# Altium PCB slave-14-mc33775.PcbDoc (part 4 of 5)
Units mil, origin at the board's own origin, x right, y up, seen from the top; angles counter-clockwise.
Board outline 6299.21 x 3937.01 mil, 6 copper layers (Top Copper, Supply, Signal Layer 1, Signal Layer 2, GND, Bot Copper), stack 69.773 mil thick; 428 components, 213 nets, 1149 pads, 1672 vias.
Unrouted connection lines stored in the file: 1.
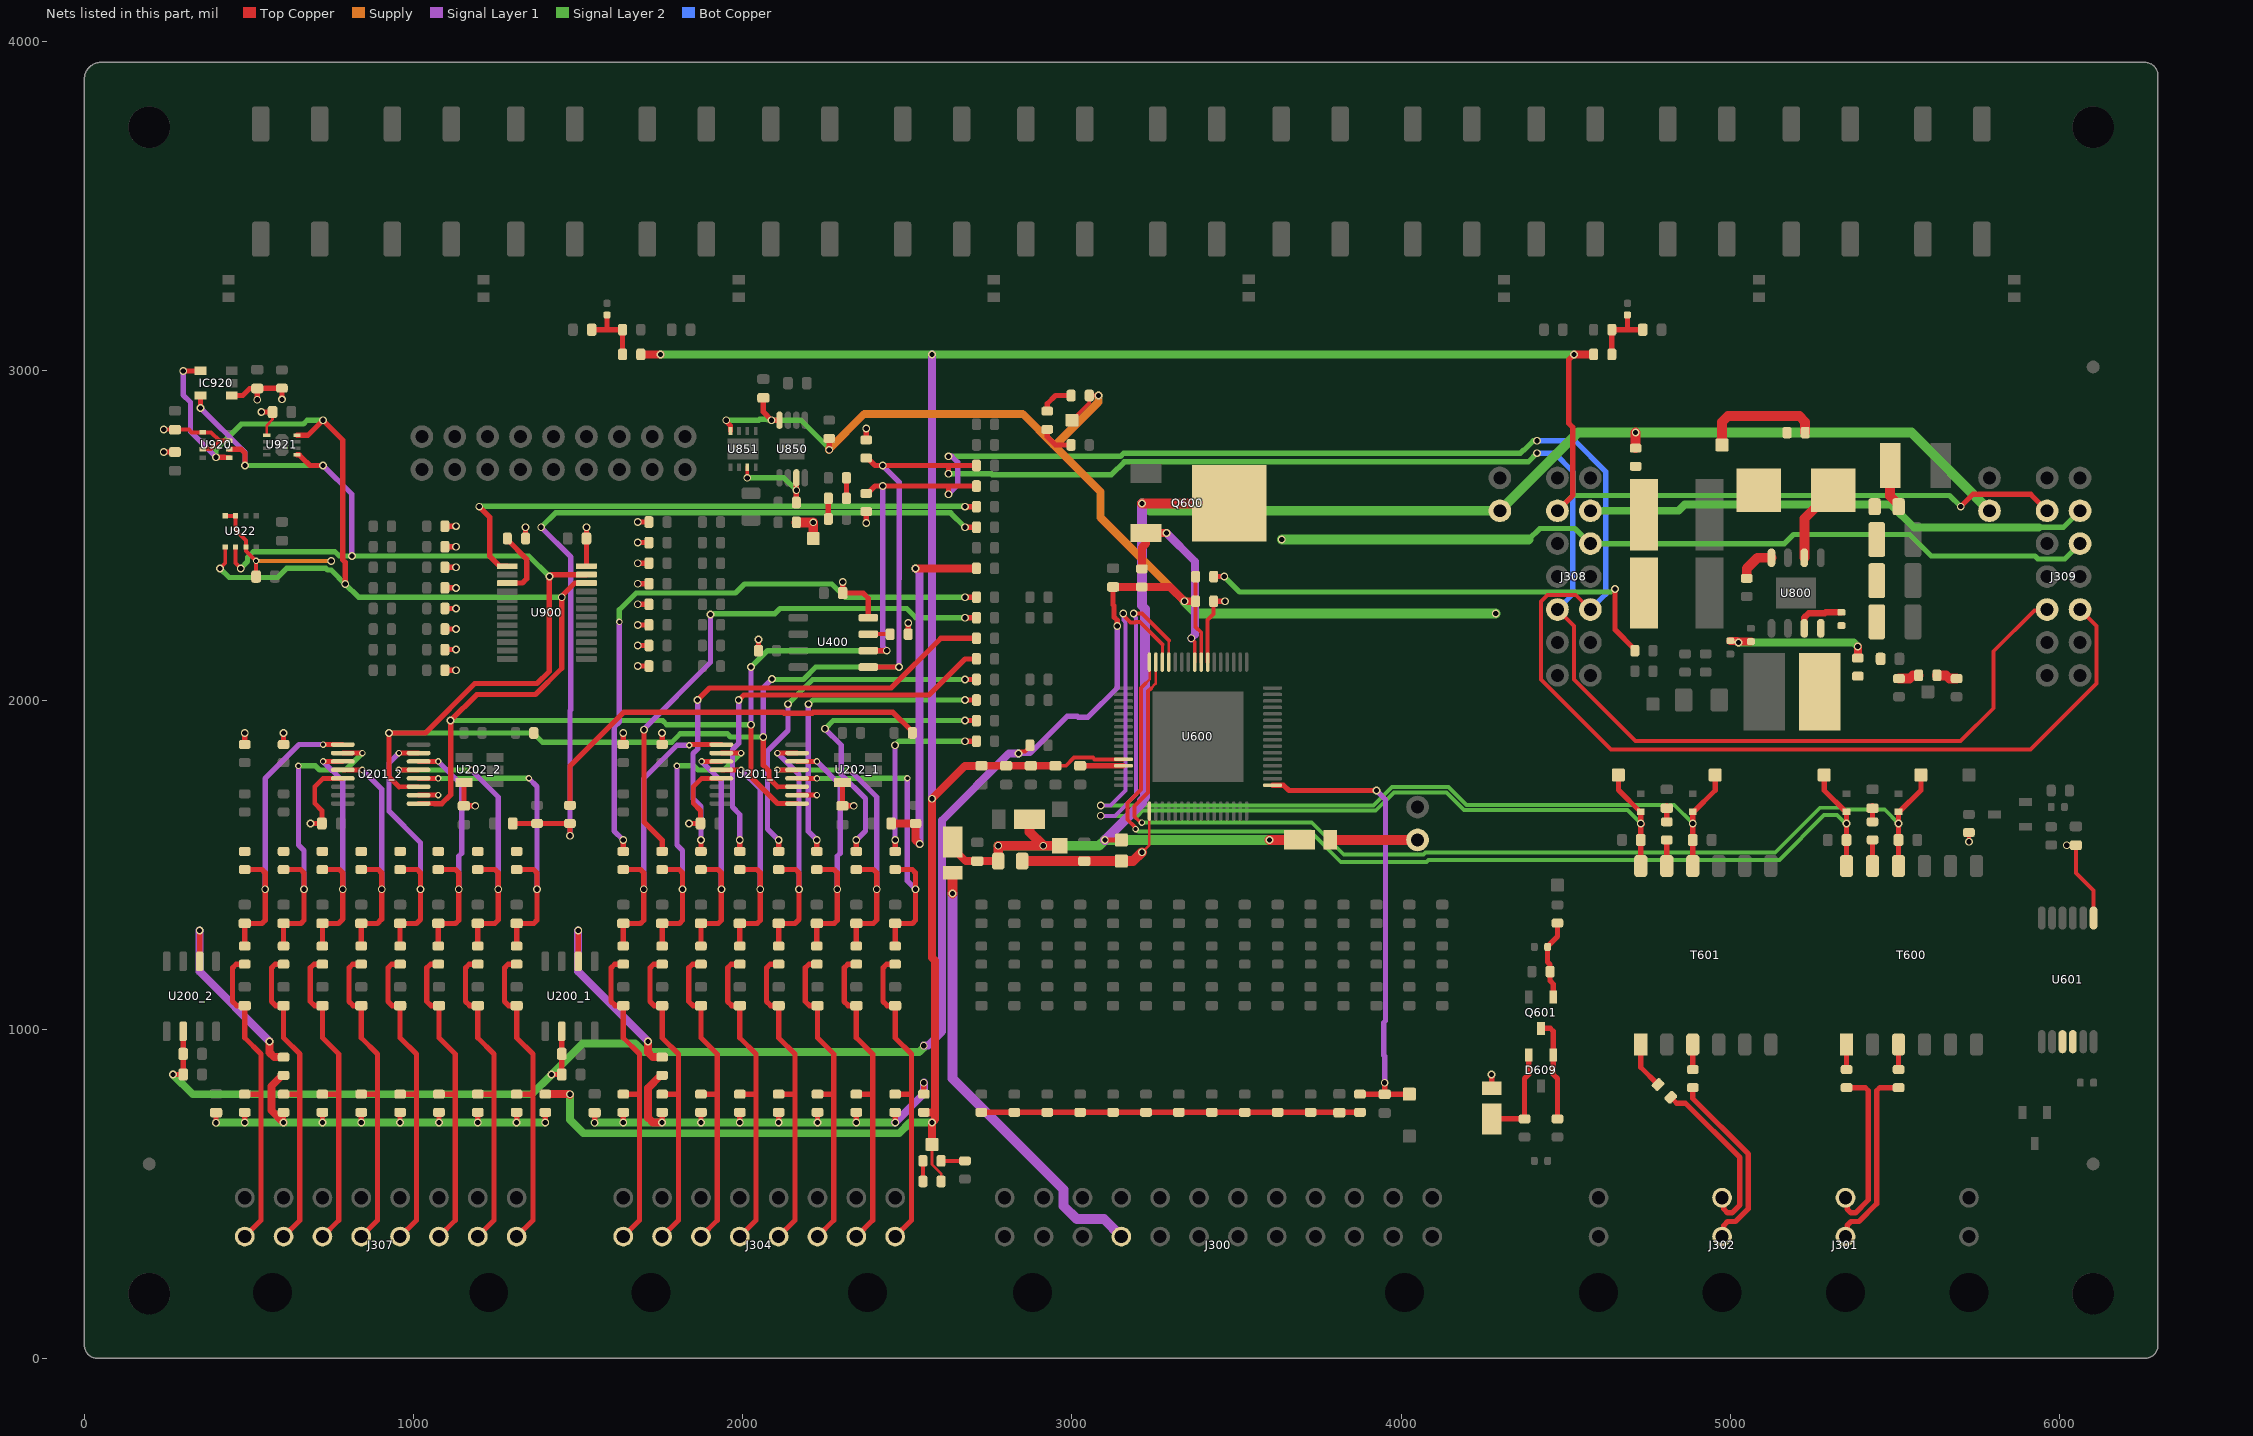
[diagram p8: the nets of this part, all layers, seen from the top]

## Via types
v1: diameter 23.62, hole 15.75, Top Copper to Bot Copper, 1585 vias
v2: diameter 19.68, hole 11.81, Top Copper to Bot Copper, 87 vias

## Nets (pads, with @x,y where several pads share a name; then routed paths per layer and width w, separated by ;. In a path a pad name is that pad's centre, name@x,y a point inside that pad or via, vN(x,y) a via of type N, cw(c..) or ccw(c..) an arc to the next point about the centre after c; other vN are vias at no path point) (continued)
I2C.SCL: IC920.4 J308.5 J309.5 R615.1 R616.1 U201_1.1 U201_2.1 U400.6 U900.22 U920.4 U921.4 U922.4 | length 11567.5
  Top Copper w12: v1(412.01,2400) 427.76,2415.75 U922.4@427.76,2465.26 ; J308.5@4575,2275 4530.55,2319.45 4444.45,2319.45 4425,2300 4425,2062.14 4637.14,1850 5912.5,1850 6112.5,2050 6112.5,2225 J309.5@6062.5,2275
  Top Copper w15: 2105.32,1685.43 U201_1.1@2165.16,1685.43
  Top Copper w16: v1(300,2999.9) 300.1,2999.9 IC920.4@352.76,2999.9 ; v1(400,2737.5) 425.63,2737.5 426.51,2736.61 U920.4@440.35,2736.61 ; U921.4@646.06,2804.53 679.53,2804.53 v1(725,2850) 784.69,2790.31 784.69,2425.98 792.13,2418.54 v1(792.13,2352.69) ; U201_2.1@1015.16,1685.43 1064.04,1685.43 1064.3,1685.18 1085.7,1685.18 1112.5,1711.98 v1(1112.5,1937.5) 1192.11,2017.11 1370.39,2017.11 1450,2096.72 v1(1450,2312.5) 1451.46,2313.96 1451.46,2317.27 1489.5,2355.32 U900.22@1525,2355.32 ; v1(2025,1925) 2025,1765.75 2105.32,1685.43 ; R616.1@2375,2627.56 2378.94,2627.56 2401.38,2650 v1(2425,2650) 2625,2650 ; U400.6@2381.3,2150 v1(2437.5,2150) ; v1(2625,2625) 2625,2650 ; R615.1@2709.94,2650 2625,2650
  Signal Layer 1 w16: v1@300,3000 300,2926.83 322.19,2904.64 322.19,2815.31 v1(400,2737.5) ; v1(2025,1925) v1(2025,2100) ; v1(2425,2650) 2425,2162.5 v1(2437.5,2150) ; v1(2625,2625) 2652.81,2652.81 2652.81,2722.19 2634.69,2740.31 v1(2625,2740.31)
  Signal Layer 2 w16: v1(400,2737.5) 400,2761.55 476.8,2838.34 665.17,2838.34 676.83,2850 v1(725,2850) ; v1(412.01,2400) 439.82,2372.19 586.56,2372.19 614.37,2400 733.34,2400 738.48,2394.86 749.96,2394.86 v1(792.13,2352.69) 832.32,2312.5 v1(1450,2312.5) ; v1(1112.5,1937.5) 1756.54,1937.5 1769.04,1925 v1(2025,1925) ; v1(2025,2100) 2075,2150 v1(2437.5,2150) ; v1(2625,2740.31) 3147.7,2740.31 3157.39,2750 4362.5,2750 4372.19,2759.69 4374.02,2759.69 4401.83,2787.5 v1(4412.5,2787.5)
  Bot Copper w16: v1(4412.5,2787.5) 4528.19,2787.5 4621.45,2694.24 4621.45,2321.45 J308.5@4575,2275
I2C.SDA: IC920.5 J308.6 J309.6 R617.1 R620.1 U201_1.3 U201_2.3 U400.5 U900.23 U920.3 U921.1 U922.3 | length 10757.6
  Top Copper w12: U922.3@459.25,2465.26 459.25,2415.75 v1(475,2400) ; J308.6@4475,2275 4525,2225 4525,2062.14 4712.14,1875 5700,1875 5800,1975 5800,2148.19 5924.05,2272.24 5959.74,2272.24 J309.6@5962.5,2275
  Top Copper w15: 955.32,1736.61 U201_2.3@1015.16,1736.61 ; 2105.32,1736.61 U201_1.3@2165.16,1736.61
  Top Copper w16: v1@351.38,2888.88 352.76,2890.26 IC920.5@352.76,2925.1 ; U920.3@440.35,2762.2 475.3,2762.2 487.5,2750 v1(487.5,2712.5) ; U921.1@646.06,2745.47 651.97,2745.47 659.7,2737.74 684.94,2712.5 v1(725,2712.5) ; 955.32,1736.61 925,1766.93 v1(925,1900) 1035.67,1900 1185.67,2050 1375,2050 1412.5,2087.5 v1(1412.5,2375) 1414.56,2375 1420.47,2380.91 U900.23@1525,2380.91 ; v1(2062.5,1887.5) 2062.5,1801.83 2079.47,1784.86 2079.47,1762.46 2105.32,1736.61 ; R617.1@2375,2734.94 2378.94,2734.94 2401.38,2712.5 v1(2425,2712.5) 2625,2712.5 ; U400.5@2381.3,2100 v1(2475,2100) ; v1(2625,2687.5) 2625,2712.5 ; R620.1@2709.94,2712.5 2625,2712.5
  Signal Layer 1 w16: v1@350,2887.5 v1(352.76,2887.5) 487.5,2752.76 v1(487.5,2712.5) ; v1(725,2712.5) 812.5,2625 v1(812.5,2437.5) ; v1(2062.5,1887.5) 2062.5,2037.53 v1(2089.22,2064.25) ; v1(2425,2712.5) 2475,2662.5 2475,2367.59 2474.75,2367.34 2474.75,2100.25 v1(2475,2100)
  Signal Layer 2 w16: v1(475,2400) 495.61,2420.61 495.61,2433.38 512.72,2450.48 761.52,2450.48 774.5,2437.5 v1(812.5,2437.5) 1350,2437.5 v1(1412.5,2375) ; v1(487.5,2712.5) v1(725,2712.5) ; v1(925,1900) 1363.62,1900 1391.72,1871.89 1784.39,1871.89 1809.89,1897.39 1953.19,1897.39 1963.08,1887.5 v1(2062.5,1887.5) ; v1@2087.5,2062.5 2184.22,2062.5 2221.72,2100 v1(2475,2100) ; v1@2087.5,2062.53 v1(2089.22,2064.25) ; v1(2625,2687.5) 2755.39,2687.5 2758.2,2684.69 3120.36,2684.69 3159.26,2723.59 4386.09,2723.59 v1(4412.5,2750)
  Bot Copper w16: v1(4412.5,2750) 4465.69,2750 4521.45,2694.24 4521.45,2321.45 J308.6@4475,2275
Imon_VDDC: Q600.3 R618.1 U600.41 | length 612.7
  Top Copper w12: v1(3362.5,2187.5) 3373.13,2176.87 U600.41@3373.13,2115.26
  Top Copper w24: R618.1@3212.5,2398.62 3212.5,2463.13 3225,2475.63 Q600.3@3225,2507.18 v1(3287.5,2507.18)
  Signal Layer 1 w24: v1(3287.5,2507.18) 3373.42,2421.26 3373.42,2198.42 v1(3362.5,2187.5)
INT: R609.1 U900.1 | length 1741.4
  Top Copper w16: v1(1199.19,2587.5) 1231,2555.69 1231,2437.7 1261.35,2407.35 1283.98,2407.35 U900.1@1284.84,2406.5 ; v1(2675,2587.5) R609.1@2709.94,2587.5
  Signal Layer 2 w16: v1(1199.19,2587.5) 1200.25,2588.56 2673.94,2588.56 v1(2675,2587.5)
MUX-DATA_IN_1: R100.1 R230_1.2 | length 1257.8
  Top Copper w16: R100.1@1475,1680.12 1475,1800 1637.5,1962.5 2123.17,1962.5 2125.98,1959.69 2211.52,1959.69 2214.33,1962.5 2456.5,1962.5 2515.06,1903.94 R230_1.2@2515.06,1900
MUX-DATA_IN_2: R230_2.2
MUX_DATA: C221_1.2 R231_1.2 R606.1 | length 1157.3
  Top Copper w24: C221_1.2@2462.99,1625 R231_1.2@2525,1625 2525,1575 v1(2537.5,1562.5) ; v1(2525,2400) R606.1@2709.94,2400
  Signal Layer 1 w24: v1(2525,2400) 2537.5,2387.5 v1(2537.5,1562.5)
MUX_DATA2: C221_2.2 R100.2 R231_2.2 R608.1 | length 2544.2
  Top Copper w16: C221_2.2@1302.85,1625 1312.99,1625 R231_2.2@1375,1625 R100.2@1475,1625 v1(1475,1587.5) ; v1(2675,2525) R608.1@2709.94,2525
  Signal Layer 1 w16: v1(1387.5,2525) 1477.81,2434.69 1477.81,1970.7 1475,1967.89 v1(1475,1587.5)
  Signal Layer 2 w16: v1(1387.5,2525) 1431.06,2568.56 2631.44,2568.56 v1(2675,2525)
NetC202_1_2: C202_1.2 R200_1.1 R203_1.1 R206_1.2 R207_1.2 R208_1.2 R209_1.2 R218_1.2 R219_1.2 R220_1.2 R221_1.2 | length 1570.5
  Top Copper w16: v1@1550,716.24 C202_1.2@1550,746.46 ; v1@1637.01,717.22 R206_1.2@1637.01,747.44 ; v1@1755,717.22 R218_1.2@1755,747.44 ; v1@1872.99,717.22 R207_1.2@1872.99,747.44 ; v1@1990.98,717.22 R219_1.2@1990.98,747.44 ; v1@2109.02,717.22 R208_1.2@2109.02,747.44 ; v1@2227.01,717.22 R220_1.2@2227.01,747.44 ; v1@2345,717.22 R209_1.2@2345,747.44 ; v1@2462.99,717.22 R221_1.2@2462.99,747.44 ; R200_1.1@2550,806.79 v1@2550,837.01
  Top Copper w24: v1(1755,716.73) 1726.56,716.73 1712.5,730.79 1712.5,821.38 1751.06,859.94 R203_1.1@1755,859.94
  Signal Layer 1 w24: v1(2462.99,716.73) 2550,803.74 v1(2550,837.5)
  Signal Layer 2 w24: v1@1549.51,716.24 v1(1550,715.75) 1550.49,716.24 2462.5,716.24 v1(2462.99,716.73)
  other v1: 1637.01,716.73 1872.99,716.73 1990.98,716.73 2109.02,716.73 2227.01,716.73 2345,716.73
NetC202_2_2: C202_2.2 R200_2.1 R203_2.1 R206_2.2 R207_2.2 R208_2.2 R209_2.2 R218_2.2 R219_2.2 R220_2.2 R221_2.2 | length 1479.5
  Top Copper w16: v1@400,716.24 C202_2.2@400,746.46 ; v1@487.01,717.22 R206_2.2@487.01,747.44 ; v1@605,717.22 R218_2.2@605,747.44 ; v1@722.99,717.22 R207_2.2@722.99,747.44 ; v1@840.98,717.22 R219_2.2@840.98,747.44 ; v1@959.02,717.22 R208_2.2@959.02,747.44 ; v1@1077.01,717.22 R220_2.2@1077.01,747.44 ; v1@1195,717.22 R209_2.2@1195,747.44 ; v1@1312.99,717.22 R221_2.2@1312.99,747.44 ; v1@1400,717.22 R200_2.1@1400,747.44
  Top Copper w24: v1(605,716.73) 567.89,753.84 567.89,826.77 601.06,859.94 R203_2.1@605,859.94
  Signal Layer 2 w24: v1(400,715.75) 400.49,716.24 1312.5,716.24 v1(1312.99,716.73) ; v1@1313.48,716.24 v1(1312.99,716.73) ; v1(1400,716.73) v1(1312.99,716.73)
  other v1: 487.01,716.73 722.99,716.73 840.98,716.73 959.02,716.73 1077.01,716.73 1195,716.73
NetC607_2: C607.2 R611.1 | length 49.8
  Top Copper w16: R611.1@5432.15,1630.12 C607.2@5432.15,1679.9
NetC610_2: C610.2 R621.1 | length 49.8
  Top Copper w16: R621.1@4807.15,1630.12 C610.2@4807.15,1679.92
NetC615_2: C615.2 Q601.G R634.2 R638.1 | length 244.8
  Top Copper w16: Q601.G@4462.4,1097.24 4462.4,1137.6 4452.56,1147.44 R638.1@4452.56,1175 4452.56,1196.72 4445.08,1204.2 C615.2@4445.08,1250 4447.32,1252.24 4447.32,1254.2 4475,1281.89 R634.2@4475,1322.44
NetC700_2: C700.2 R700.1 R702.2 R704.1 | length 213.7
  Top Copper w16: C700.2@1541.04,3125 1587.5,3125 ; R704.1@1587.5,3169.78 1587.5,3125 ; R700.1@1634.94,3050 1634.94,3103.28 R702.2@1634.94,3125 1587.5,3125
NetC702_2: C702.2 R701.1 R703.2 R705.1 | length 213.9
  Top Copper w16: R701.1@4640.06,3050 4640.06,3071.72 R703.2@4640.06,3125 4687.01,3125 ; R705.1@4687.5,3169.78 4687.5,3125.49 4687.01,3125 ; C702.2@4733.96,3125 4687.01,3125
NetC804_2: C804.2 R802.1 | length 135.6
  Top Copper w30: C804.2@5485.73,2712.5 5485.73,2620.08 5511.42,2594.39 R802.1@5511.42,2587.5
NetC805_1: C805.1 U800.7 | length 151.8
  Top Copper w20: U800.7@5225,2217.72 5225,2250.5 5238.25,2263.76 5286.89,2263.76 5289.47,2266.34 C805.1@5337.5,2266.34
NetC808_1: C808.1 C809.2 R805.2 | length 468.2
  Top Copper w24: C808.1@5000,2179.92 5020.08,2179.92 v1(5025,2175) 5027.56,2177.56 C809.2@5062.5,2177.56 ; R805.2@5387.5,2127.56 v1(5387.5,2162.5)
  Signal Layer 2 w24: v1(5025,2175) 5375,2175 v1(5387.5,2162.5)
NetD608_1: D608.1 D609.2 R628.1 | length 299.9
  Top Copper w16: D608.1@4275,727.56 R628.1@4375,727.56 4375,850 4387.6,862.6 D609.2@4387.6,922.24
NetD609_1: D609.1 Q601.D R632.1 | length 312.3
  Top Copper w16: Q601.D@4425,1002.76 4453.03,1002.76 4462.4,993.38 4462.4,862.6 4475,850 R632.1@4475,727.56
NetLD600_1: LD600.1 R604.2 | length 105.2
  Top Copper w16: LD600.1@2925,2822.44 2925,2800 2950,2775 R604.2@2997.44,2775
NetLD600_2: LD600.2 R602.1 | length 105.2
  Top Copper w16: LD600.2@2925,2877.56 2925,2900 2950,2925 R602.1@2997.44,2925
NetLD601_1: LD601.1 R605.2 | length 72.4
  Top Copper w12: LD601.1@2602.56,600 R605.2@2675,600
NetLD601_2: LD601.2 R603.1 | length 62.5
  Top Copper w12: R603.1@2547.44,537.5 2547.44,578.28 LD601.2@2547.44,600
NetLD800_1: LD800.1 R804.2 | length 64.1
  Top Copper w30: LD800.1@5627.56,2075 5655.84,2075 5665.78,2065.06 R804.2@5687.5,2065.06
NetLD800_2: LD800.2 R801.1 | length 64.1
  Top Copper w30: R801.1@5512.5,2065.06 5544.72,2065.06 5554.66,2075 LD800.2@5572.44,2075
NetLD850_1: LD850.1 R854.2 | length 62.5
  Top Copper w16: LD850.1@2315.06,2612.5 2315.06,2653.28 R854.2@2315.06,2675
NetLD850_2: LD850.2 R853.1 | length 62.5
  Top Copper w16: R853.1@2259.94,2550 LD850.2@2259.94,2612.5
NetR203_1_2: R203_1.2 U200_1.6 | length 600.9
  Top Copper w16: U200_1.6@1500,1206.3 v1(1500,1300)
  Top Copper w24: v1(1712.5,962.5) 1712.5,929.12 1726.56,915.06 R203_1.2@1755,915.06
  Signal Layer 1 w24: v1(1500,1300) 1500,1175 v1(1712.5,962.5)
NetR203_2_2: R203_2.2 U200_2.6 | length 600.9
  Top Copper w16: U200_2.6@350,1206.3 v1(350,1300)
  Top Copper w24: v1(562.5,962.5) 562.5,929.12 576.56,915.06 R203_2.2@605,915.06
  Signal Layer 1 w24: v1(350,1300) 350,1175 v1(562.5,962.5)
NetR601_2: R601.2 R807.1 | length 1454.6
  Top Copper w16: R601.2@3430.68,2375 v1(3462.5,2375) ; v1(4650,2337.5) 4650,2213.88 4709.94,2153.94 R807.1@4709.94,2150
  Signal Layer 2 w16: v1(3462.5,2375) 3508.95,2328.55 4638.99,2328.55 4647.94,2337.5 v1(4650,2337.5)
NetR610_1: R610.1 T600.3 | length 75.8
  Top Copper w16: R610.1@5511.15,877.56 T600.3@5511.15,953.35
NetR611_2: R611.2 T600.11 | length 79.2
  Top Copper w16: T600.11@5432.15,1495.85 R611.2@5432.15,1575
NetR612_1: R612.1 T600.1 | length 75.8
  Top Copper w16: R612.1@5353.15,877.56 T600.1@5353.15,953.35
NetR619_1: R619.1 T601.3 | length 75.8
  Top Copper w16: R619.1@4886.15,877.56 T601.3@4886.15,953.35
NetR621_2: R621.2 T601.11 | length 79.2
  Top Copper w16: T601.11@4807.15,1495.85 R621.2@4807.15,1575
NetR622_1: R622.1 T601.1 | length 143
  Top Copper w16: T601.1@4728.15,953.35 4728.15,884.35 R622.1@4780.51,831.99
PE_NRESET: R916.2 U900.3 | length 210.6
  Top Copper w16: U900.3@1284.84,2355.32 1330.32,2355.32 1343.37,2368.37 1343.37,2428.28 1284.84,2486.81 R916.2@1284.84,2490.75
PG_LDO: R852.1 U850.3 U851.3 | length 272
  Top Copper w12: v1(2013.68,2675) U851.3@2013.68,2707.38
  Top Copper w16: R852.1@2162.8,2600 v1(2162.8,2637.45) U850.3@2162.8,2674.9
  Signal Layer 2 w16: v1(2013.68,2675) 2125.25,2675 v1(2162.8,2637.45)
Ron: R809.2 U800.4 | length 118.6
  Top Copper w30: R809.2@5050,2369.78 5050,2400 5082.28,2432.28 U800.4@5125,2432.28
RXTXH_N: C608.1 D605.1 T600.12 TPL_H_N.1 U600.48 | length 3122.3
  Top Copper w8: 3224.12,2050.88 3236.18,2062.93 3236.18,2088.34 3235.84,2088.68 3235.84,2114.75 U600.48@3235.33,2115.26
  Top Copper w12: v2(3193.36,1607.84) 3193.36,1609.92 3189.51,1613.76 3189.51,1615.52 3168.72,1636.32 3168.72,1687.33 3209.44,1728.06 3209.44,2036.19 3224.12,2050.88
  Top Copper w16: TPL_H_N.1@5285.1,1772.24 5285.1,1726.02 5351.18,1659.94 D605.1@5353.15,1659.94 v1(5353.15,1625) C608.1@5353.15,1575 T600.12@5353.15,1495.85
  Signal Layer 2 w12: v2(3193.36,1607.84) 3195.44,1607.84 3202.47,1600.81 3724.19,1600.81 3816.59,1508.41 4077.39,1508.41 4083.52,1514.55 5149.11,1514.55 5285.37,1650.81 5324.19,1650.81 5350,1625 v1(5353.15,1625)
RXTXH_P: C602.2 D604.1 T600.10 TPL_H_P.1 U600.47 | length 3248.9
  Top Copper w8: 3239.68,2035.32 3254.18,2049.82 3254.18,2088.34 3254.52,2088.68 3254.52,2114.75 U600.47@3255.02,2115.26
  Top Copper w12: v2(3212.5,1627.84) 3210.42,1627.84 3206.58,1631.68 3204.46,1631.68 3190.72,1645.43 3190.72,1678.22 3231.44,1718.94 3231.44,2027.08 3239.68,2035.32
  Top Copper w16: T600.10@5511.15,1495.85 C602.2@5511.15,1575 v1(5511.15,1625) D604.1@5511.15,1659.94 5513.12,1659.94 5579.2,1726.02 TPL_H_P.1@5579.2,1772.24
  Signal Layer 2 w12: v2(3212.5,1627.84) 3728.47,1627.84 3825.76,1530.55 4068.41,1530.55 4074.41,1536.55 5136.55,1536.55 5272.81,1672.81 5333.31,1672.81 5339.31,1666.81 5469.34,1666.81 v1(5511.15,1625)
RXTXL_N: C612.1 D607.1 T601.12 TPL_L_N.1 U600.45 | length 2911.1
  Top Copper w8: U600.45@3294.63,2115.26 3294.63,2180.37
  Top Copper w12: v1(3187.5,2262.5) 3212.5,2262.5 3294.63,2180.37
  Top Copper w16: TPL_L_N.1@4660.1,1772.24 4660.1,1727.11 D607.1@4728.15,1659.06 ; T601.12@4728.15,1495.85 C612.1@4728.15,1575 4728.15,1618.26 v1@4732.82,1622.94 ; v1@4728.15,1622.94 v1(4728.15,1625) D607.1@4728.15,1659.06 ; D607.1@4728.15,1659.94 D607.1@4728.15,1659.06
  Signal Layer 1 w12: v1(3087.5,1648.19) 3130.41,1648.19 3194.92,1712.71 3194.92,2248.79 3193.31,2250.4 3193.31,2253.54 3187.5,2259.36 v1(3187.5,2262.5)
  Signal Layer 2 w12: v1(3087.5,1648.19) 3199.13,1648.19 3214.75,1663.81 3922.94,1663.81 3978.58,1719.45 4137.54,1719.45 4191.66,1665.34 4687.81,1665.34 v1(4728.15,1625) ; v1@4728.15,1625.81 v1@4728.96,1625
RXTXL_P: C609.2 D606.1 T601.10 TPL_L_P.1 U600.46 | length 3020
  Top Copper w8: 3274.63,2168.89 3275,2168.52 U600.46@3275,2121.46
  Top Copper w12: v1(3155.89,2263.23) 3158.11,2261 3158.11,2255.39 3178.22,2235.27 3192,2235.27 3193.42,2236.69 3207.2,2236.69 3274.63,2169.26 3274.63,2168.89
  Top Copper w16: T601.10@4886.15,1495.85 C609.2@4886.15,1575 v1(4886.15,1625) D606.1@4886.15,1659.94 4888.12,1659.94 4954.2,1726.02 TPL_L_P.1@4954.2,1772.24
  Signal Layer 1 w12: v1(3087.5,1679.81) 3117.31,1679.81 3163.31,1725.81 3163.31,2235.69 3155.89,2243.12 v1(3155.89,2263.23)
  Signal Layer 2 w12: v1(3087.5,1679.81) 3916.31,1679.81 3971.95,1735.45 4144.17,1735.45 4198.28,1681.34 4829.81,1681.34 v1(4886.15,1625) v1@4887.5,1625
S1_1: C212_1.2 R210_1.1 R222_1.1 U201_1.4 | length 1025.7
  Top Copper w15: U201_1.4@2165.16,1762.2 v2(2225,1762.2)
  Top Copper w16: R222_1.1@2462.99,1252.56 C212_1.2@2462.99,1318.75 ; C212_1.2@2462.99,1321.46 2515.63,1321.46 2525,1330.83 v1(2525,1425) 2525,1475 2515.06,1484.94 R210_1.1@2462.99,1484.94
  Signal Layer 1 w16: v2(2500,1762.5) 2500,1450 v1(2525,1425)
  Signal Layer 2 w16: v2(2225,1762.2) 2225.55,1761.66 2362.08,1761.66 2362.92,1762.5 v2(2500,1762.5)
S1_2: C212_2.2 R210_2.1 R222_2.1 U201_2.4 | length 1025.4
  Top Copper w15: U201_2.4@1015.16,1762.2 v2(1075,1762.2)
  Top Copper w16: R222_2.1@1312.99,1252.56 C212_2.2@1312.99,1318.75 ; C212_2.2@1312.99,1321.46 1365.21,1321.46 1375,1331.25 1375,1475 1365.06,1484.94 R210_2.1@1312.99,1484.94
  Signal Layer 1 w16: v2(1350,1762.5) 1375,1737.5 v1(1375,1425)
  Signal Layer 2 w16: v2(1075,1762.2) 1075.55,1761.66 1212.08,1761.66 1212.92,1762.5 v2(1350,1762.5)
S2_1: C213_1.2 R211_1.1 R223_1.1 U201_1.5 | length 1008.7
  Top Copper w15: v2(2105.32,1787.8) U201_1.5@2165.16,1787.8
  Top Copper w16: R223_1.1@2345,1252.56 C213_1.2@2345,1309.65 ; C213_1.2@2345,1321.46 2396.46,1321.46 2407.01,1332.01 2407.01,1475 2397.07,1484.94 R211_1.1@2345,1484.94
  Signal Layer 1 w16: v2(2325,1787.5) 2407.01,1705.49 v1(2407.01,1425)
  Signal Layer 2 w15: v2(2105.32,1787.8) 2235.25,1787.8 2235.54,1787.5 v2(2325,1787.5)
S2_2: C213_2.2 R211_2.1 R223_2.1 U201_2.5 | length 1017.8
  Top Copper w15: v2(955.32,1787.8) U201_2.5@1015.16,1787.8
  Top Copper w16: R223_2.1@1195,1252.56 C213_2.2@1195,1318.75 ; C213_2.2@1195,1321.46 1246.46,1321.46 1257.01,1332.01 1257.01,1475 1247.07,1484.94 R211_2.1@1195,1484.94
  Signal Layer 1 w16: v2(1175,1787.5) 1257.01,1705.49 v1(1257.01,1425)
  Signal Layer 2 w15: v2(955.32,1787.8) 1085.25,1787.8 1085.54,1787.5 v2(1175,1787.5)
S3_1: C214_1.2 R212_1.1 R224_1.1 U201_1.6 | length 823.7
  Top Copper w15: U201_1.6@2165.16,1813.39 v2(2225,1813.39)
  Top Copper w16: R224_1.1@2225,1252.56 C214_1.2@2225,1318.75 ; C214_1.2@2225,1321.46 2277.64,1321.46 2287.01,1330.83 v1(2287.01,1425) 2287.01,1475 2277.07,1484.94 R212_1.1@2225,1484.94
  Signal Layer 1 w16: v2(2225,1813.39) 2295.92,1742.46 2295.92,1534.48 2287.01,1525.56 v1(2287.01,1425)
S3_2: C214_2.2 R212_2.1 R224_2.1 U201_2.6 | length 823.7
  Top Copper w15: U201_2.6@1015.16,1813.39 v2(1075,1813.39)
  Top Copper w16: R224_2.1@1075,1252.56 C214_2.2@1075,1318.75 ; C214_2.2@1075,1321.46 1127.64,1321.46 1137.01,1330.83 1137.01,1475 1127.07,1484.94 R212_2.1@1075,1484.94
  Signal Layer 1 w16: v2(1075,1813.39) 1145.92,1742.46 1145.92,1534.48 1137.01,1525.56 v1(1137.01,1425)
S4_1: C215_1.2 R213_1.1 R225_1.1 U201_1.7 | length 848.1
  Top Copper w15: v2(2105.32,1838.98) U201_1.7@2165.16,1838.98
  Top Copper w16: R225_1.1@2109.02,1252.56 C215_1.2@2109.02,1325 ; C215_1.2@2109.02,1321.46 2158.96,1321.46 2171.02,1333.52 2171.02,1475 2161.08,1484.94 R213_1.1@2109.02,1484.94
  Signal Layer 1 w16: v2(2105.32,1838.98) 2171.02,1773.27 v1(2171.02,1425)
S4_2: C215_2.2 R213_2.1 R225_2.1 U201_2.7 | length 866.9
  Top Copper w15: v2(955.32,1838.98) U201_2.7@1015.16,1838.98
  Top Copper w16: R225_2.1@959.02,1252.56 C215_2.2@959.02,1318.75 ; C215_2.2@959.02,1321.46 1008.96,1321.46 1021.02,1333.52 1021.02,1475 1011.08,1484.94 R213_2.1@959.02,1484.94
  Signal Layer 1 w16: v2(955.32,1838.98) 925,1808.66 925,1662.5 1021.02,1566.48 v1(1021.02,1425)
S5_1: C216_1.2 R214_1.1 R226_1.1 U201_1.12 | length 789.2
  Top Copper w15: U201_1.12@1934.84,1787.8 v2(1994.69,1787.8)
  Top Copper w16: R226_1.1@1990.98,1252.56 C216_1.2@1990.98,1318.75 ; C216_1.2@1990.98,1321.46 2043.62,1321.46 2052.99,1330.83 2052.99,1475 2043.05,1484.94 R214_1.1@1990.98,1484.94
  Signal Layer 1 w16: v2(1994.69,1787.8) 2052.99,1729.49 v1(2052.99,1425)
S5_2: C216_2.2 R214_2.1 R226_2.1 U201_2.12 | length 787.2
  Top Copper w15: U201_2.12@784.84,1787.8 v2(844.69,1787.8)
  Top Copper w16: R226_2.1@840.98,1252.56 C216_2.2@840.98,1318.75 ; C216_2.2@840.98,1321.46 890.21,1321.46 902.99,1334.24 902.99,1475 893.05,1484.94 R214_2.1@840.98,1484.94
  Signal Layer 1 w16: v2(844.69,1787.8) 902.99,1729.49 v1(902.99,1425)
S6_1: C217_1.2 R215_1.1 R227_1.1 U201_1.11 | length 815.5
  Top Copper w15: v2(1875,1813.39) U201_1.11@1934.84,1813.39
  Top Copper w16: R227_1.1@1872.99,1252.56 C217_1.2@1872.99,1318.75 ; C217_1.2@1872.99,1321.46 1925.63,1321.46 1935,1330.83 1935,1475 1925.06,1484.94 R215_1.1@1872.99,1484.94
  Signal Layer 1 w16: v2(1875,1813.39) 1935,1753.39 v1(1935,1425)
S6_2: C217_2.2 R215_2.1 R227_2.1 U201_2.11 | length 813
  Top Copper w15: v2(725,1813.39) U201_2.11@784.84,1813.39
  Top Copper w16: R227_2.1@722.99,1252.56 C217_2.2@722.99,1318.75 ; C217_2.2@722.99,1321.46 771.46,1321.46 785,1335 785,1475 775.06,1484.94 R215_2.1@722.99,1484.94
  Signal Layer 1 w16: v2(725,1813.39) 785,1753.39 v1(785,1425)
S7_1: C218_1.2 R216_1.1 R228_1.1 U201_1.10 | length 1005.4
  Top Copper w15: U201_1.10@1934.84,1838.98 v2(1994.69,1838.98)
  Top Copper w16: R228_1.1@1755,1252.56 C218_1.2@1755,1318.75 ; C218_1.2@1755,1321.46 1807.64,1321.46 1817.01,1330.83 1817.01,1475 1807.07,1484.94 R216_1.1@1755,1484.94
  Signal Layer 1 w16: v2(1800,1800) 1800,1559.36 1817.01,1542.35 v1(1817.01,1425)
  Signal Layer 2 w16: v2(1800,1800) 1851.84,1800 1864.3,1787.54 1943.25,1787.54 v2(1994.69,1838.98)
S7_2: C218_2.2 R216_2.1 R228_2.1 U201_2.10 | length 1005.4
  Top Copper w15: U201_2.10@784.84,1838.98 v2(844.69,1838.98)
  Top Copper w16: R228_2.1@605,1252.56 C218_2.2@605,1318.75 ; C218_2.2@605,1321.46 657.64,1321.46 667.01,1330.83 667.01,1475 657.07,1484.94 R216_2.1@605,1484.94
  Signal Layer 1 w16: v2(650,1800) 650,1559.36 667.01,1542.35 v1(667.01,1425)
  Signal Layer 2 w16: v2(650,1800) 701.84,1800 714.3,1787.54 793.25,1787.54 v2(844.69,1838.98)
S8_1: C219_1.2 R217_1.1 R229_1.1 U201_1.9 | length 957.4
  Top Copper w15: v2(1837.5,1862.5) 1838.77,1862.5 1840.83,1864.57 U201_1.9@1934.84,1864.57
  Top Copper w16: R229_1.1@1637.01,1252.56 C219_1.2@1637.01,1318.75 ; C219_1.2@1637.01,1321.46 1689.64,1321.46 1699.02,1330.83 1699.02,1475 1689.07,1484.94 R217_1.1@1637.01,1484.94
  Signal Layer 1 w16: v1(1699.02,1425) 1699.02,1761.52 1800,1862.5 v2(1837.5,1862.5)
S8_2: C219_2.2 R217_2.1 R229_2.1 U201_2.9 | length 957.6
  Top Copper w15: v2(725,1864.57) U201_2.9@784.84,1864.57
  Top Copper w16: R229_2.1@487.01,1252.56 C219_2.2@487.01,1318.75 ; C219_2.2@487.01,1321.46 539.64,1321.46 549.02,1330.83 549.02,1475 539.07,1484.94 R217_2.1@487.01,1484.94
  Signal Layer 1 w16: v1(549.02,1425) 549.02,1761.52 652.32,1864.82 724.75,1864.82 v2(725,1864.57)
SW: C805.2 L801.1 R805.1 U800.8
T-SENSOR_0: C204_1.2 J304.1 R221_1.1 R222_1.2 | length 977.9
  Top Copper w16: J304.1@2462.99,370 2512.5,419.51 2512.5,802.56 ; R221_1.1@2462.99,802.56 2512.5,802.56 ; R222_1.2@2462.99,1197.44 2437.12,1197.44 2425.98,1186.3 2425.98,1084.28 2438.8,1071.46 C204_1.2@2462.99,1071.46 2462.99,981.79 2462.99,973.92 2512.5,924.41 2512.5,802.56
T-SENSOR_1: C205_1.2 J304.2 R209_1.1 R223_1.2 | length 977.9
  Top Copper w16: J304.2@2345,370 2394.51,419.51 2394.51,924.41 2345,973.92 2345,981.79 C205_1.2@2345,1071.46 2320.81,1071.46 2307.99,1084.28 2307.99,1186.3 2319.13,1197.44 R223_1.2@2345,1197.44 ; R209_1.1@2345,802.56 2394.51,802.56
T-SENSOR_2: C206_1.2 J304.3 R220_1.1 R224_1.2 | length 977.9
  Top Copper w16: J304.3@2227.01,370 2276.52,419.51 2276.52,924.41 2227.01,973.92 2227.01,981.79 C206_1.2@2227.01,1071.46 2202.82,1071.46 2190,1084.28 2190,1186.3 2201.14,1197.44 R224_1.2@2227.01,1197.44 ; R220_1.1@2227.01,802.56 2276.52,802.56
T-SENSOR_3: C207_1.2 J304.4 R208_1.1 R225_1.2 | length 977.9
  Top Copper w16: J304.4@2109.02,370 2158.52,419.51 2158.52,924.41 2109.02,973.92 2109.02,981.79 C207_1.2@2109.02,1071.46 2084.83,1071.46 2072.01,1084.28 2072.01,1186.3 2083.15,1197.44 R225_1.2@2109.02,1197.44 ; R208_1.1@2109.02,802.56 2158.52,802.56
T-SENSOR_4: C208_1.2 J304.5 R219_1.1 R226_1.2 | length 977.9
  Top Copper w16: J304.5@1990.98,370 2040.49,419.51 2040.49,924.41 1990.98,973.92 1990.98,981.79 C208_1.2@1990.98,1071.46 1966.8,1071.46 1953.98,1084.28 1953.98,1186.3 1965.11,1197.44 R226_1.2@1990.98,1197.44 ; R219_1.1@1990.98,802.56 2040.49,802.56
T-SENSOR_5: C209_1.2 J304.6 R207_1.1 R227_1.2 | length 977.9
  Top Copper w16: J304.6@1872.99,370 1922.5,419.51 1922.5,924.41 1872.99,973.92 1872.99,981.79 C209_1.2@1872.99,1071.46 1848.8,1071.46 1835.98,1084.28 1835.98,1186.3 1847.12,1197.44 R227_1.2@1872.99,1197.44 ; R207_1.1@1872.99,802.56 1922.5,802.56
T-SENSOR_6: C210_1.2 J304.7 R218_1.1 R228_1.2 | length 977.9
  Top Copper w16: J304.7@1755,370 1804.51,419.51 1804.51,924.41 1755,973.92 1755,981.79 C210_1.2@1755,1071.46 1730.81,1071.46 1717.99,1084.28 1717.99,1186.3 1729.13,1197.44 R228_1.2@1755,1197.44 ; R218_1.1@1755,802.56 1804.51,802.56
T-SENSOR_7: C211_1.2 J304.8 R206_1.1 R229_1.2 | length 977.9
  Top Copper w16: J304.8@1637.01,370 1686.52,419.51 1686.52,924.41 1637.01,973.92 1637.01,981.79 C211_1.2@1637.01,1071.46 1612.82,1071.46 1600,1084.28 1600,1186.3 1611.14,1197.44 R229_1.2@1637.01,1197.44 ; R206_1.1@1637.01,802.56 1686.52,802.56
T-SENSOR_8: C204_2.2 J307.1 R221_2.1 R222_2.2 | length 977.9
  Top Copper w16: J307.1@1312.99,370 1362.5,419.51 1362.5,802.56 ; R221_2.1@1312.99,802.56 1362.5,802.56 ; R222_2.2@1312.99,1197.44 1287.12,1197.44 1275.98,1186.3 1275.98,1084.28 1288.8,1071.46 C204_2.2@1312.99,1071.46 1312.99,981.79 1312.99,973.92 1362.5,924.41 1362.5,802.56
T-SENSOR_9: C205_2.2 J307.2 R209_2.1 R223_2.2 | length 977.9
  Top Copper w16: J307.2@1195,370 1244.51,419.51 1244.51,802.56 ; R209_2.1@1195,802.56 1244.51,802.56 ; R223_2.2@1195,1197.44 1169.13,1197.44 1157.99,1186.3 1157.99,1084.28 1170.81,1071.46 C205_2.2@1195,1071.46 1195,981.79 1195,973.92 1244.51,924.41 1244.51,802.56
T-SENSOR_10: C206_2.2 J307.3 R220_2.1 R224_2.2 | length 977.9
  Top Copper w16: J307.3@1077.01,370 1126.52,419.51 1126.52,802.56 ; R220_2.1@1077.01,802.56 1126.52,802.56 ; R224_2.2@1077.01,1197.44 1051.14,1197.44 1040,1186.3 1040,1084.28 1052.82,1071.46 C206_2.2@1077.01,1071.46 1077.01,981.79 1077.01,973.92 1126.52,924.41 1126.52,802.56
T-SENSOR_11: C207_2.2 J307.4 R208_2.1 R225_2.2 | length 977.9
  Top Copper w16: J307.4@959.02,370 1008.52,419.51 1008.52,802.56 ; R208_2.1@959.02,802.56 1008.52,802.56 ; R225_2.2@959.02,1197.44 933.15,1197.44 922.01,1186.3 922.01,1084.28 934.83,1071.46 C207_2.2@959.02,1071.46 959.02,981.79 959.02,973.92 1008.52,924.41 1008.52,802.56
T-SENSOR_12: C208_2.2 J307.5 R219_2.1 R226_2.2 | length 977.9
  Top Copper w16: J307.5@840.98,370 890.49,419.51 890.49,802.56 ; R219_2.1@840.98,802.56 890.49,802.56 ; R226_2.2@840.98,1197.44 815.12,1197.44 803.98,1186.3 803.98,1084.28 816.8,1071.46 C208_2.2@840.98,1071.46 840.98,981.79 840.98,973.92 890.49,924.41 890.49,802.56
T-SENSOR_13: C209_2.2 J307.6 R207_2.1 R227_2.2 | length 977.9
  Top Copper w16: J307.6@722.99,370 772.5,419.51 772.5,802.56 ; R207_2.1@722.99,802.56 772.5,802.56 ; R227_2.2@722.99,1197.44 697.12,1197.44 685.98,1186.3 685.98,1084.28 698.8,1071.46 C209_2.2@722.99,1071.46 722.99,981.79 722.99,973.92 772.5,924.41 772.5,802.56
T-SENSOR_14: C210_2.2 J307.7 R218_2.1 R228_2.2 | length 977.9
  Top Copper w16: J307.7@605,370 654.51,419.51 654.51,802.56 ; R218_2.1@605,802.56 654.51,802.56 ; R228_2.2@605,1197.44 579.13,1197.44 567.99,1186.3 567.99,1084.28 580.81,1071.46 C210_2.2@605,1071.46 605,981.79 605,973.92 654.51,924.41 654.51,802.56
T-SENSOR_15: C211_2.2 J307.8 R206_2.1 R229_2.2 | length 977.9
  Top Copper w16: J307.8@487.01,370 536.52,419.51 536.52,802.56 ; R206_2.1@487.01,802.56 536.52,802.56 ; R229_2.2@487.01,1197.44 461.14,1197.44 450,1186.3 450,1084.28 462.82,1071.46 C211_2.2@487.01,1071.46 487.01,981.79 487.01,973.92 536.52,924.41 536.52,802.56
T_FILT0: R210_1.2 R629.1 | length 574.8
  Top Copper w16: R210_1.2@2462.99,1540.06 v1@2462.99,1574.21 ; v1(2675,1875) R629.1@2709.94,1875
  Signal Layer 1 w16: v1(2462.5,1862.47) 2462.75,1862.23 2462.75,1574.95 v1(2462.99,1574.7)
  Signal Layer 2 w16: v1(2462.5,1862.47) 2475.03,1875 v1(2675,1875)
T_FILT0_2: R210_2.2
T_FILT1: R211_1.2 R630.1 | length 904.6
  Top Copper w16: R211_1.2@2345,1540.06 v1@2345,1574.21 ; v1(2675,1937.5) R630.1@2709.94,1937.5
  Signal Layer 1 w16: v1(2250,1912.5) 2299.16,1863.34 2299.16,1774.21 2372.81,1700.55 2372.81,1602.52 v1(2345,1574.7)
  Signal Layer 2 w16: v1(2250,1912.5) 2275,1937.5 v1(2675,1937.5)
T_FILT1_2: R211_2.2
T_FILT2: R212_1.2 R631.1 | length 973.1
  Top Copper w16: R212_1.2@2225,1540.06 v1@2225,1574.21 ; v1(2675,2000) R631.1@2709.94,2000
  Signal Layer 1 w16: v1(2200,1987.5) 2199.16,1986.66 2199.16,1600.55 v1(2225,1574.7)
  Signal Layer 2 w16: v1(2200,1987.5) 2212.5,2000 v1(2675,2000)
T_FILT2_2: R212_2.2
T_FILT3: R213_1.2 R633.1 | length 1090.4
  Top Copper w16: R213_1.2@2109.02,1540.06 v1@2109.02,1574.21 ; v1(2675,2062.5) R633.1@2709.94,2062.5
  Signal Layer 1 w16: v1(2109.02,1574.7) 2075,1608.72 2075,1845.21 2137.5,1907.71 v1(2137.5,1987.5)
  Signal Layer 2 w16: v1(2137.5,1987.5) 2212.5,2062.5 v1(2675,2062.5)
T_FILT3_2: R213_2.2
T_FILT4: R214_1.2 R635.1 | length 1250.6
  Top Copper w16: v1(1987.5,2000) 2002.81,2015.31 2565.31,2015.31 2675,2125 R635.1@2709.94,2125 ; R214_1.2@1990.98,1540.06 v1@1990.98,1574.21
  Signal Layer 1 w16: v1(1987.5,2000) 1987.5,1868.34 1968.84,1849.68 1968.84,1674.73 1991,1652.57 v1(1990.98,1574.7)
T_FILT4_2: R214_2.2
T_FILT5: R215_1.2 R636.1 | length 1400.7
  Top Copper w16: v1(1862.5,2000) 1898.94,2036.44 2450.77,2036.44 2601.83,2187.5 R636.1@2709.94,2187.5 ; R215_1.2@1872.99,1540.06 v1@1872.99,1574.21
  Signal Layer 1 w16: v1(1862.5,2000) 1863.34,1999.16 1863.34,1851.8 1849.16,1837.61 1849.16,1700.32 1872.99,1676.48 v1(1872.99,1574.7)
T_FILT5_2: R215_2.2
T_FILT6: R216_1.2 R639.1 | length 1652.7
  Top Copper w16: v1(1700,1909.69) 1700,1629.7 1755,1574.7 ; R216_1.2@1755,1540.06 1755,1574.21 ; v1(2675,2250) R639.1@2709.94,2250
  Signal Layer 1 w16: v1(1700,1909.69) 1700,1912.5 1902.16,2114.66 v1(1902.16,2260.11)
  Signal Layer 2 w16: v1(1902.16,2260.11) 1903.62,2261.57 1911.57,2261.57 1912.5,2262.5 2098.17,2262.5 2113.48,2277.81 2498.04,2277.81 2525.85,2250 v1(2675,2250)
T_FILT6_2: R216_2.2
T_FILT7: R217_1.2 R640.1 | length 1885.9
  Top Copper w16: R217_1.2@1637.01,1540.06 v1@1637.01,1574.21 ; v1(2675,2312.5) R640.1@2709.94,2312.5
  Signal Layer 1 w16: v2(1625,2237.5) 1625,1933.04 1609.2,1917.24 1609.2,1602.52 v1(1637.01,1574.7)
  Signal Layer 2 w16: v2(1625,2237.5) 1625,2274.17 1676.26,2325.44 1977.96,2325.44 2005.33,2352.81 2270.36,2352.81 2310.67,2312.5 v1(2675,2312.5)
T_FILT7_2: R217_2.2
TPL_H._N: J301.2 R612.2 | length 523.4
  Top Copper w16: J301.2@5350,487.99 5355.12,482.87 5355.12,453.99 5367.12,442 5380.37,442 5419.15,480.77 5419.15,813.07 5409.78,822.44 R612.2@5353.15,822.44
TPL_H._P: J301.1 R610.2 | length 566.4
  Top Copper w16: J301.1@5350,370 5355.12,375.12 5355.12,404 5367.12,416 5391.14,416 5445.15,470 5445.15,813.07 5454.52,822.44 R610.2@5511.15,822.44
TPL_L._N: J302.2 R622.2 | length 529.3
  Top Copper w16: R622.2@4819.49,793.01 4837.5,775 4863.7,775 5029,609.7 5029,465.62 5005.37,442 4992.12,442 4980.12,453.99 4980.12,482.87 J302.2@4975,487.99
TPL_L._P: J302.1 R619.2 | length 569.6
  Top Copper w16: R619.2@4886.15,822.44 4886.15,789.32 5055,620.47 5055,454.86 5016.14,416 4992.12,416 4980.12,404 4980.12,375.12 J302.1@4975,370
VAUX: C603.2 C604.2 C605.2 C606.2 J308.12 J309.12 R200_1.2 R200_2.2 R603.2 R700.2 R701.2 U600.60 Vaux.1 | length 9430.7
  Top Copper w8: Vaux.1@2575,650 2575,588.79 2602.56,561.23 R603.2@2602.56,537.5
  Top Copper w12: C606.2@2950,1800.3 2981.72,1800.3 3006.48,1825.06 3063.44,1825.06 3068.52,1819.98 U600.60@3156.59,1819.98
  Top Copper w16: 2702,1800 2702.3,1800.3 ; J308.12@4475,2575 4521.45,2621.45 4521.45,2828.31 4509.69,2840.07 4509.69,3034.69 v1(4525,3050) ; v1(5700,2587.5) 5737.5,2625 5912.5,2625 J309.12@5962.5,2575
  Top Copper w24: R200_2.2@1400,802.56 1472.44,802.56 v1@1475,800 ; R700.2@1690.06,3050 v1(1750,3050) ; R200_1.2@2550,747.44 2575,747.44 ; Vaux.1@2575,650 v1(2575,716.73) 2583.72,725.45 2583.72,1208.37 2575,1217.08 v1(2575,1700) 2675,1800 2702,1800 ; 2702.3,1800.3 C603.2@2725,1800.3 C604.2@2800,1800.3 C605.2@2875,1800.3 C606.2@2950,1800.3 ; v1(4525,3050) R701.2@4584.94,3050
  Signal Layer 1 w24: v1(2575,1700) v1(2575,3050)
  Signal Layer 2 w16: J308.12@4475,2575 4521.45,2621.45 5666.05,2621.45 v1(5700,2587.5)
  Signal Layer 2 w24: v1@1475,800 1475,725 1516.06,683.94 2475.18,683.94 2507.98,716.73 v1(2575,716.73) ; v1(1750,3050) v1(2575,3050) v1(4525,3050)
  other v1: 1475,802.56
VBAT: C601.2 R600.1 U600.1 Vbat.1 | length 509.2
  Top Copper w8: v1(3212.5,1537.5) 3235.33,1560.33 U600.1@3235.33,1662.5
  Top Copper w30: R600.1@2848.92,1510.63 2937.5,1510.63 C601.2@3037.5,1510.63 3185.63,1510.63 v1(3212.5,1537.5)
VBAT_con: D600.2 J300.9 | length 1365.6
  Top Copper w30: v1(2637.5,1412.5) D600.2@2637.5,1475
  Signal Layer 1 w30: v1(2637.5,1412.5) 2637.5,850 2974.55,512.95 2974.55,462.95 3014.59,422.91 3097.09,422.91 J300.9@3150,370
VBAT_con_ext: C600.2 D600.1 D601.1 D602.1 D603.1 J311.1 J312.1 Q600.2 Q600.4 R600.2 R800.1 Vbat_con_ext.1 | length 5581.8
  Top Copper w16: v1(3100,1575) Vbat_con_ext.1@3150,1575
  Top Copper w24: D600.1@2637.5,1550.79 2677.66,1510.63 C600.2@2712.5,1510.63 R600.2@2776.08,1510.63
  Top Copper w30: D600.1@2637.5,1550.79 D600.1@2637.5,1568.5 ; R600.2@2776.08,1510.63 v1(2776.08,1557.38) v1(2913.04,1557.38) ; D603.1@2870.96,1637.5 2870.96,1599.46 v1(2913.04,1557.38) ; D602.1@2962.5,1557.38 v1(2913.04,1557.38) ; v1(3212.5,2597.34) Q600.2@3412.01,2597.34 ; v1(3600,1575) D601.1@3691.54,1575 ; R800.1@4712.5,2765.06 v1(4712.5,2812.5)
  Signal Layer 1 w30: v1(3100,1575) 3212.5,1687.5 3212.5,1694.93 3222.31,1704.74 3222.31,2276.92 3212.5,2286.73 v1(3212.5,2597.34)
  Signal Layer 2 w30: v1(2776.08,1557.38) v1(2913.04,1557.38) 3082.38,1557.38 v1(3100,1575) v1(3600,1575) ; v1(3212.5,2597.34) 3215.16,2597.34 3237.5,2575 J311.1@4300,2575 4300,2575.59 4536.91,2812.5 v1(4712.5,2812.5) 5550,2812.5 J312.1@5787.5,2575
VBAT_con_ext_emi: C802.2 C803.2 C806.2 C807.2 L800.2 R802.2 R803.2 U800.2 Vin_DCDC.1 | length 612.4
  Top Copper w30: Vin_DCDC.1@4975,2775 4975,2844.93 4992.57,2862.5 5209.99,2862.5 5227.56,2844.93 R803.2@5227.56,2812.5 ; U800.2@5225,2432.28 5225,2551.28 5311.22,2637.5 L800.2@5313.19,2637.5
VBAT_con_ext_lim: C800.2 C801.2 L800.1 R800.2 R803.1
VBAT_ext: D601.2 J310.1 | length 265
  Top Copper w30: D601.2@3785.04,1575 J310.1@4050,1575
Vdd2_unused: U601.10
VDDA: C613.2 U600.61 | length 131.6
  Top Copper w16: C613.2@3025,1800.3 U600.61@3156.59,1800.3
VDDC: C200_1.2 C200_2.2 C201_1.2 C201_2.2 C611.2 C617.2 C850.2 D608.2 J308.11 J309.11 R601.1 R602.2 R618.2 R627.1 R637.2 R641.1 R851.2 U200_1.2 U200_2.2 U600.40 U601.1 U850.8 U851.8 Vddc.1 | length 10121.9
  Top Copper w12: v1(2837.5,1837.5) 2843.97,1843.97 2857.85,1843.97 2872.44,1858.56 R627.1@2872.44,1862.5 ; Vddc.1@3000,2850 3052.56,2902.56 R602.2@3052.56,2925 v1(3080.45,2925) ; R601.1@3375.57,2375 R637.2@3375.57,2300 3375.57,2222.19 3392.82,2204.94 U600.40@3392.82,2115.26 ; v1(5725,1569.45) R641.1@5725,1597.34 ; v1(6022.11,1558.96) C617.2@6050,1558.96 6050,1475 6103.74,1421.26 U601.1@6103.74,1337.99
  Top Copper w16: v1@269.78,862.5 C201_2.2@300,862.5 C200_2.2@300,925 U200_2.2@300,993.7 ; v1@1419.78,862.5 C201_1.2@1450,862.5 C200_1.2@1450,925 U200_1.2@1450,993.7 ; v1(1950,2850.1) v1@1950.05,2850.05 ; v1@1950.1,2850.1 v1@1950.05,2850.05 ; U851.8@1962.5,2817.62 1962.5,2833.43 1951.46,2844.47 1951.46,2848.64 v1@1950.05,2850.05 ; C850.2@2062.5,2917.91 2062.5,2875 v1(2087.5,2850) 2097.67,2850 2097.77,2850.1 U850.8@2111.61,2850.1 ; v1(2262.5,2760.04) R851.2@2262.5,2794.98 ; C611.2@3125,2334.65 3125,2289.33 3128.08,2286.26 3128.08,2251.71 3137.5,2242.28 v1(3137.5,2225) ; D608.2@4275,821.06 v1(4275,862.5)
  Top Copper w24: C611.2@3131.7,2343.5 R618.2@3212.5,2343.5 ; R618.2@3218.22,2343.5 3298.11,2343.5 v1(3341.61,2300) R637.2@3375.57,2300
  Signal Layer 1 w16: v1(2837.5,1837.5) 2872.03,1837.5 2984.88,1950.34 3015.78,1950.34 3018.12,1948 3049.02,1948 3137.5,2036.48 v1(3137.5,2225)
  Signal Layer 1 w24: v1(2550,950) 2562.5,950 2605.69,993.19 2605.69,1634.93 2808.26,1837.5 v1(2837.5,1837.5)
  Signal Layer 2 w16: v1(1950,2850.1) 1950.1,2850 2048.17,2850 2050.98,2852.81 2074.02,2852.81 2075.37,2851.46 2086.04,2851.46 v1(2087.5,2850) ; v1@2087.6,2850 2176.83,2850 2261.04,2765.79 2261.04,2761.5 v1(2262.5,2760.04) ; 5937.5,2525 6012.5,2525 J309.11@6062.5,2575
  Signal Layer 2 w24: v1(269.29,862.5) 329.35,802.44 1359.23,802.44 v1(1419.29,862.5) 1513.6,956.81 1673.2,956.81 1699.32,930.69 2535.94,930.69 2550,944.75 v1(2550,950) ; J308.11@4575,2575 4842.51,2575 4861.82,2594.31 5487.8,2594.31 5557.56,2524.55 5937.05,2524.55 5937.5,2525
  Signal Layer 2 w30: v1(3341.61,2300) 3379.11,2262.5 v1(4287.5,2262.5)
  Supply w24: v1(2262.5,2760.04) 2262.5,2762.5 2369.31,2869.31 2850.24,2869.31 2944.55,2775 ; v1(3080.45,2925) 3080.45,2905.45 2950,2775 2944.55,2775 ; v1(3341.61,2300) 3086.77,2554.84 3086.77,2632.78 2944.55,2775
VDDIO: 3.3V_LDO.1 C203_1.2 C203_2.2 C220_1.2 C220_2.2 C400.2 C900.2 C920.2 C921.2 C922.2 C924.2 C925.2 IC920.1 J308.9 J309.9 R201_1.2 R201_2.2 R202_1.2 R202_2.2 R400.2 R401.2 R616.2 R617.2 R637.1 R850.2 R900.2 R901.2 R902.2 R903.2 R904.2 R905.2 R906.2 R907.2 R908.2 R909.2 R910.2 R911.2 R912.2 R913.2 R914.2 R915.2 R916.1 R920.2 U201_1.2 U201_1.13 U201_2.2 U201_2.13 U202_1.5 U202_2.5 U400.8 U600.39 U900.24 U920.2 U920.6 U920.8 U921.5 U922.2 U922.5 U922.6 | length 5947.7
  Top Copper w8: U921.5@553.94,2804.53 553.94,2834.78 571.46,2852.3 C922.2@571.46,2875
  Top Copper w12: v1(241.04,2821.46) 317.66,2821.46 325.73,2813.39 385.06,2813.39 410.65,2787.8 ; U920.6@359.65,2762.2 385.06,2762.2 410.65,2787.8 ; U922.5@427.76,2559.74 U922.6@459.25,2559.74 459.25,2515.75 490.75,2484.25 U922.2@490.75,2465.26 490.75,2453.38 v2(521.46,2422.67) C924.2@521.46,2375 ; U920.2@440.35,2787.8 410.65,2787.8 ; U600.39@3412.5,2115.26 3412.5,2243.75 3430.68,2261.93 R637.1@3430.68,2300
  Top Copper w15: C203_2.2@721.46,1625 721.46,1664.33 699.66,1686.13 699.66,1736.86 725,1762.2 U201_2.13@784.84,1762.2 ; U201_2.2@1015.16,1711.02 v2(1075,1711.02) ; C220_2.2@1152.76,1678.54 U202_2.5@1152.76,1750.1 ; C203_1.2@1871.46,1625 1871.46,1664.33 1849.66,1686.13 1849.66,1736.86 1875,1762.2 U201_1.13@1934.84,1762.2 ; U201_1.2@2165.16,1711.02 v2(2225,1711.02) ; C220_1.2@2302.76,1678.54 U202_1.5@2302.76,1750.1
  Top Copper w16: v1(241.04,2753.54) C920.2@275,2753.54 ; IC920.1@447.24,2925.1 480.94,2925.1 502.3,2946.46 C925.2@525,2946.46 ; R201_2.2@487.01,1865.06 v1@487.01,1899.21 ; v1(525,2912.5) C925.2@525,2946.46 ; v1(537.5,2875) C922.2@571.46,2875 ; v1(600,2913.48) R920.2@600,2947.44 548.69,2947.44 547.7,2946.46 C925.2@525,2946.46 ; R202_2.2@605,1865.06 v1@605,1899.21 ; v1@687.3,1625 C203_2.2@721.46,1625 ; R902.2@1094.98,2090.75 v1(1128.94,2090.75) ; R912.2@1094.98,2153.25 v1(1128.94,2153.25) ; R906.2@1094.98,2215.75 v1(1128.94,2215.75) ; R901.2@1094.98,2278.25 v1(1128.94,2278.25) ; R911.2@1094.98,2340.75 v1(1128.94,2340.75) ; R905.2@1094.98,2403.25 v1(1128.94,2403.25) ; R900.2@1094.98,2465.75 v1(1128.94,2465.75) ; R910.2@1094.98,2528.25 v1(1128.94,2528.25) ; C220_2.2@1152.76,1678.54 v1@1186.91,1678.54 ; R916.1@1339.96,2490.75 v1(1339.96,2524.7) ; U900.24@1525,2406.5 C900.2@1525,2490.75 v1(1525,2524.7) ; R201_1.2@1637.01,1865.06 v1@1637.01,1899.21 ; v1(1680.91,2103.25) R907.2@1714.86,2103.25 ; v1(1680.91,2165.75) R913.2@1714.86,2165.75 ; v1(1680.91,2228.25) R903.2@1714.86,2228.25 ; v1(1680.91,2290.75) R908.2@1714.86,2290.75 ; v1(1680.91,2353.25) R914.2@1714.86,2353.25 ; v1(1680.91,2415.75) R904.2@1714.86,2415.75 ; v1(1680.91,2478.25) R909.2@1714.86,2478.25 ; v1(1680.91,2540.75) R915.2@1714.86,2540.75 ; R202_1.2@1755,1865.06 v1@1755,1899.21 ; v1@1837.3,1625 C203_1.2@1871.46,1625 ; R401.2@2047.44,2150 v1(2047.44,2183.96) ; C220_1.2@2302.76,1678.54 v1@2336.91,1678.54 ; v1(2303.54,2358.96) C400.2@2303.54,2325 2365.63,2325 2381.3,2309.33 U400.8@2381.3,2250 ; v1(2375,2537.5) R616.2@2375,2572.44 ; R617.2@2375,2790.06 v1(2375,2825) ; R400.2@2502.56,2200 v1(2502.56,2233.96) ; R637.1@3430.68,2300 v1(3464.64,2300)
  Top Copper w30: R850.2@2162.8,2539.79 v1(2214.17,2539.79) 3.3V_LDO.1@2214.17,2490.43
  Signal Layer 2 w16: 4387.5,2487.5 4421.45,2521.45 4528.55,2521.45 J308.9@4575,2475 5164.33,2475 5192.14,2502.81 5545.36,2502.81 5610.72,2437.45 5925.51,2437.45 5934.4,2428.55 6016.05,2428.55 J309.9@6062.5,2475
  Signal Layer 2 w30: v1(3637.5,2487.5) 4387.5,2487.5
  Supply w12: v2(521.46,2422.67) v1(750,2422.67)
  other v1: 686.81,1625 1836.81,1625 1187.4,1678.54 2337.4,1678.54 487.01,1899.7 605,1899.7 1637.01,1899.7 1755,1899.7
VMODULE: C531.2 R515.1 U600.17 Vmodule.1 | length 1409.3
  Top Copper w16: U600.17@3609.35,1741.24 3642.88,1741.24 3659.12,1725 v1(3925,1725) ; R515.1@3875,802.56 3949.02,802.56 3950,803.54 v1(3950,837.5) ; C531.2@3950,802.56 Vmodule.1@4025,802.56
  Signal Layer 1 w16: v1(3925,1725) 3952.81,1697.19 3952.81,1025.98 3947.19,1020.36 3947.19,920.97 3950,918.16 v1(3950,837.5)
Vmodule_unfiltered: C530.2 R515.2 R516.2 R517.2 R518.2 R519.2 R520.2 R521.2 R522.2 R523.2 R524.2 R525.2 R526.2 | length 1150
  Top Copper w16: R526.2@2725,747.44 R525.2@2825,747.44 R524.2@2925,747.44 R523.2@3025,747.44 R522.2@3125,747.44 R521.2@3225,747.44 R520.2@3325,747.44 R519.2@3425,747.44 R518.2@3525,747.44 R517.2@3625,747.44 R516.2@3725,747.44 R515.2@3875,747.44
Vout_unused: U601.9
W\C\: R400.1 U400.7 | length 66.1
  Top Copper w12: U400.7@2381.3,2200 R400.1@2447.44,2200
pads on no net: FD_LL.0 FD_LR.0 FD_UR.0 J300. J300.10 J300.11 J300.12 J300.21 J300.22 J300.23 J300.24 J301. J302. J304. J305. J306. J307. MP_LL.Hole_3.2_Iso MP_LR.Hole_3.2_Iso MP_UL.Hole_3.2_Iso MP_UR.Hole_3.2_Iso T600.2 T600.4 T600.5 T600.6 T600.7 T600.8 T600.9 T601.2 T601.4 T601.5 T601.6 T601.7 T601.8 T601.9 U200_1.1 U200_1.3 U200_1.5 U200_1.7 U200_1.8 U200_2.1 U200_2.3 U200_2.5 U200_2.7 U200_2.8 U600.44 U601.4 U601.5 U601.6 U800.6 U850.2 U850.6 U851.2 U851.6

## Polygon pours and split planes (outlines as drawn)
no net on Top Overlay "Polygon_23_NoNet" (solid): 5588.79,3019.28 5596.33,3017.7 5601.01,3015 5603.01,3012.86 5604.44,3010.24 5605.59,3003.78 5605.21,3000.08 5604.08,2996.81 5602.25,2993.99 5599.77,2991.64 5592.94,2988.41 5583.94,2987.29 5577.79,2987.61 5572.51,2988.76 5567.64,2990.89 5562.64,2994.3 5560.91,2995.51 5559.09,2996.06 5556.78,2995.15 5555.8,2992.8 5556.52,2990.91 5558.18,2989.32 5564.05,2985.49 5570.07,2983.04 5576.5,2981.75 5583.57,2981.37 5589.92,2981.77 5595.59,2982.95 5600.54,2984.88 5604.71,2987.5 5608.05,2990.77 5610.49,2994.65 5612,2999.08 5612.52,3004.02 5612.03,3008.75 5610.6,3013.04 5608.28,3016.79 5605.13,3019.91 5599.07,3023.24 5589.71,3025.31 5580.51,3026.67 5573.19,3028.43 5567.92,3031.52 5564.65,3035.94 5563.58,3042.05 5564.91,3048.88 5568.75,3054.05 5574.88,3057.34 5583.09,3058.5 5592.5,3057.38 5600.88,3053.12 5604.38,3051.54 5606.78,3052.58 5607.51,3054.52 5606.75,3056.38 5605,3057.89 5600.04,3060.82 5595.09,3062.79 5589.71,3063.9 5583.45,3064.25 5577.61,3063.85 5572.38,3062.68 5567.82,3060.77 5563.98,3058.18 5560.9,3054.94 5558.64,3051.1 5557.24,3046.71 5556.77,3041.83 5557.19,3037.32 5558.46,3033.3 5560.58,3029.78 5563.56,3026.79 5570.3,3022.87 5578.86,3020.76
no net on Top Overlay "Polygon_25_NoNet" (solid): 5411.06,2982.05 5425.29,2982.05 5430.88,2982.4 5435.78,2983.48 5440.09,2985.25 5443.75,2987.72 5446.7,2990.88 5448.87,2994.72 5450.22,2999.22 5450.68,3004.37 5449.68,3011.02 5446.79,3016.68 5442.16,3021.14 5436.37,3023.95 5441.55,3026.52 5445.78,3030.74 5448.44,3036.06 5449.37,3042.16 5448.88,3046.98 5447.48,3051.23 5445.24,3054.91 5442.25,3057.96 5438.6,3060.38 5434.36,3062.14 5424.51,3063.57 5397.03,3063.57 5395.43,3063.46 5393.88,3062.66 5393.04,3061.17 5392.92,3059.65 5392.92,2985.91 5393.04,2984.43 5393.88,2982.95 5395.42,2982.15 5396.96,2982.05 5411.06,2982.05 5411.96,2987.96 5399.94,2987.96 5399.83,3020.76 5411.83,3020.76 5411.51,3026.68 5399.83,3026.68 5399.83,3057.65 5423.75,3057.65 5431.01,3056.77 5436.96,3054.02 5439.23,3051.89 5440.96,3049.23 5442.06,3046 5442.45,3042.19 5442.06,3038.34 5440.96,3035.1 5439.23,3032.44 5436.96,3030.32 5431.01,3027.56 5423.77,3026.68 5411.51,3026.68 5411.83,3020.76 5424.7,3020.76 5432.56,3019.63 5438.56,3016.39 5442.4,3011.24 5443.76,3004.37 5442.4,2997.49 5438.56,2992.34 5432.56,2989.09 5424.73,2987.96 5411.96,2987.96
